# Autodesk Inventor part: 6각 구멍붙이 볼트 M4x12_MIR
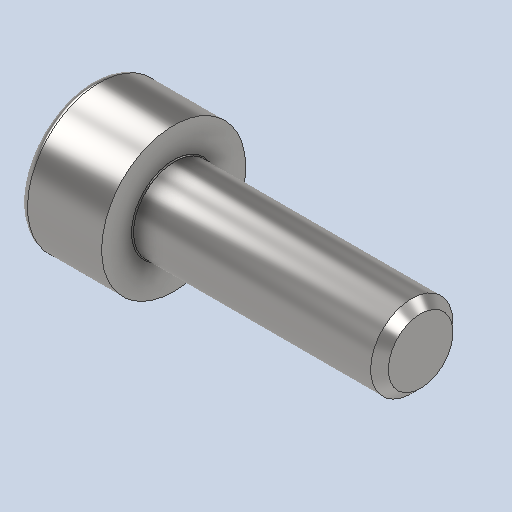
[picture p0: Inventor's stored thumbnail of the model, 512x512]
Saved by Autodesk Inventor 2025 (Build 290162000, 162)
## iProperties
Created: 2026-04
Part Number: 6각 구멍붙이 볼트 M4x12_MIR
Material: 강철, 연강
Description: 6각머리 태핑 나사
Document SubType Name: Modeling
Designer: KDI
Density: 7.85 g/cm^3
Appearance: 기본값
Author: jhkim
Sending System: Autodesk Inventor 2027
Preprocessor: ST-DEVELOPER v20.1
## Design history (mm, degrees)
derived "6각 구멍붙이 볼트 M4x12.ipt"
feature "솔리드1::6각 구멍붙이 볼트 M4x12.ipt" dims "d0" = 10
tag "피쳐 태그1"
node "솔리드1"
